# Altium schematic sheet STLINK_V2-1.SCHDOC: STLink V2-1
size A4; Author: Ph.A; SheetNumber: 7; SheetTotal: 8
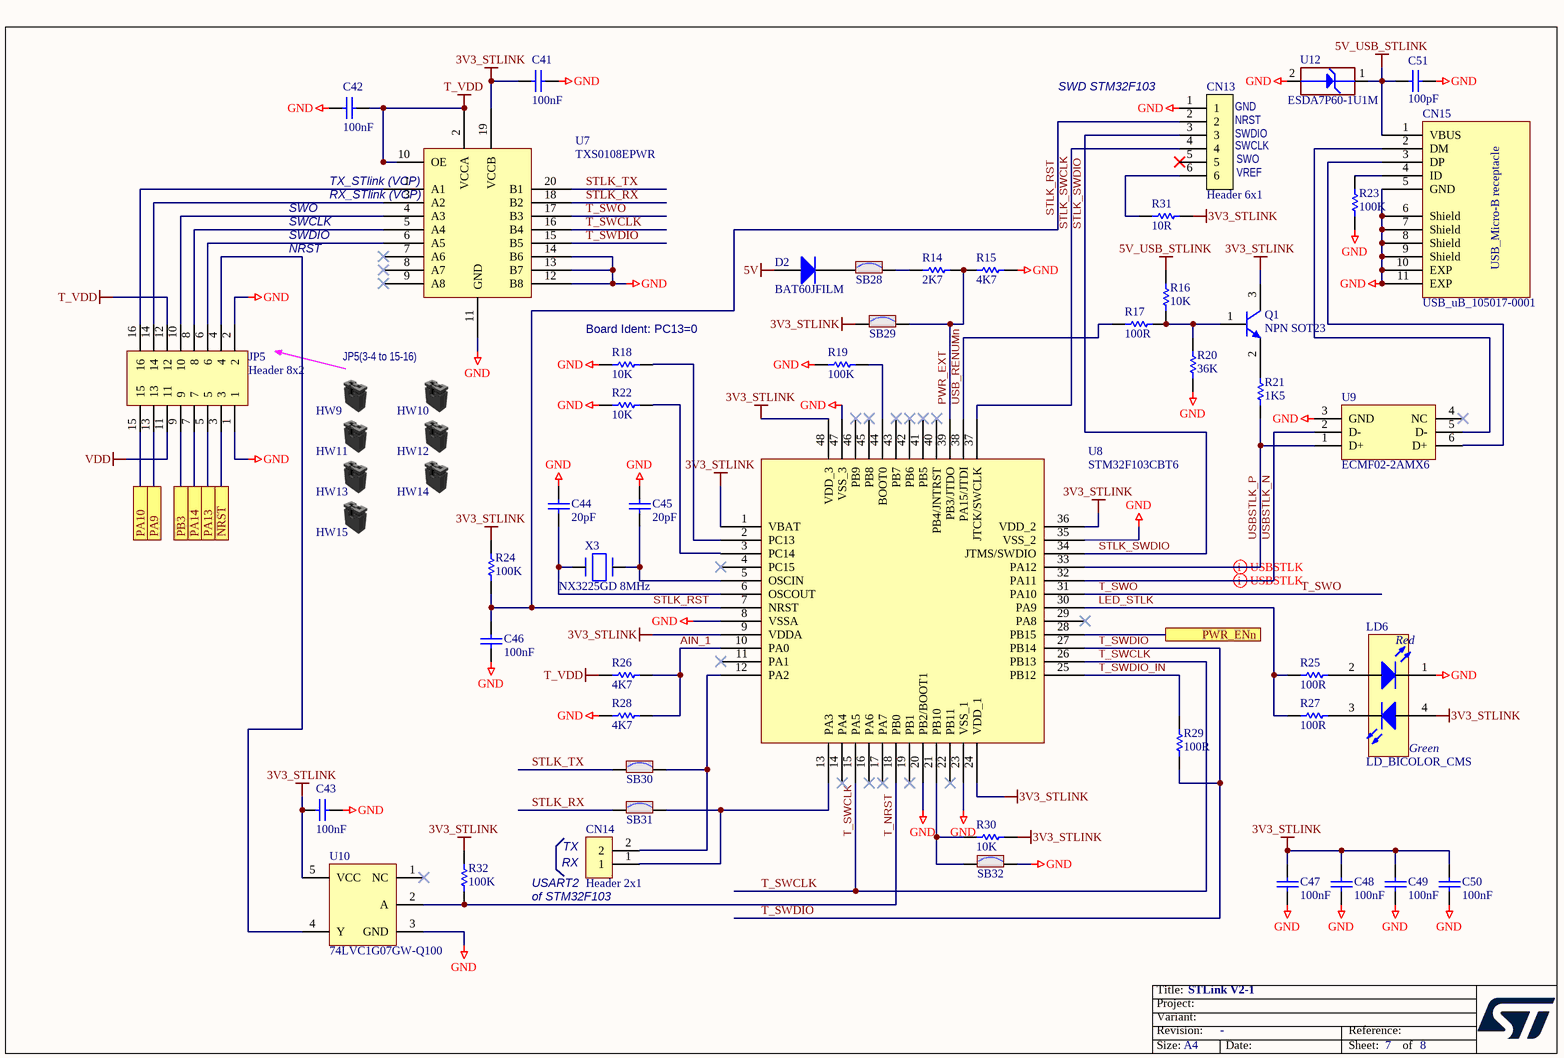
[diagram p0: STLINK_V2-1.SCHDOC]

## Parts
C41  value 100nF  [C0402]  (hidden comment: Capacitor)
C42  value 100nF  [C0402]  (hidden comment: Capacitor)
C43  value 100nF  [C0402]  (hidden comment: Capacitor)
C44  value 20pF  [C0402]  (hidden comment: Capacitor)
C45  value 20pF  [C0402]  (hidden comment: Capacitor)
C46  value 100nF  [C0402]  (hidden comment: Capacitor)
C47  value 100nF  [C0402]  (hidden comment: Capacitor)
C48  value 100nF  [C0402]  (hidden comment: Capacitor)
C49  value 100nF  [C0402]  (hidden comment: Capacitor)
C50  value 100nF  [C0402]  (hidden comment: Capacitor)
C51  value 100pF  [C0402]  (hidden comment: Capacitor)
CN13  Header 6x1  [CON_SAMTEC_TSW-106-07-X-S]
CN14  Header 2x1  [CON_SAMTEC_TSW-102-07-G-S]
CN15  value USB_uB_105017-0001  [CON_USBMICROB_MOLEX_105017-0001_H2P90]  (hidden comment: USB_uB_105017.0001)
D2  BAT60JFILM  [DIO_SOD323]
HW9  Shunt Black 2.54mm  (value not drawn)  (mechanical)
HW10  Shunt Black 2.54mm  (value not drawn)  (mechanical)
HW11  Shunt Black 2.54mm  (value not drawn)  (mechanical)
HW12  Shunt Black 2.54mm  (value not drawn)  (mechanical)
HW13  Shunt Black 2.54mm  (value not drawn)  (mechanical)
HW14  Shunt Black 2.54mm  (value not drawn)  (mechanical)
HW15  Shunt Black 2.54mm  (value not drawn)  (mechanical)
JP5  Header 8x2  [CON_SAMTEC_TSW-108-07-X-D]
LD6  LD_BICOLOR_CMS  [LED_BI-GR_HSMF-A201-A00J1]
Q1  value NPN SOT23  [NPN_SOT23]  (hidden comment: 9013-SOT23)
R14  value 2K7  [R0402]  (hidden comment: Resistor)
R15  value 4K7  [R0402]  (hidden comment: Resistor)
R16  value 10K  [R0402]  (hidden comment: Resistor)
R17  value 100R  [R0402]  (hidden comment: Resistor)
R18  value 10K  [R0402]  (hidden comment: Resistor)
R19  value 100K  [R0402]  (hidden comment: Resistor)
R20  value 36K  [R0402]  (hidden comment: Resistor)
R21  value 1K5  [R0402]  (hidden comment: Resistor)
R22  value 10K  [R0402]  (hidden comment: Resistor)
R23  value 100K  [R0402]  (hidden comment: Resistor)
R24  value 100K  [R0402]  (hidden comment: Resistor)
R25  value 100R  [R0402]  (hidden comment: Resistor)
R26  value 4K7  [R0402]  (hidden comment: Resistor)
R27  value 100R  [R0402]  (hidden comment: Resistor)
R28  value 4K7  [R0402]  (hidden comment: Resistor)
R29  value 100R  [R0402]  (hidden comment: Resistor)
R30  value 10K  [R0402]  (hidden comment: Resistor)
R31  value 10R  [R0402]  (hidden comment: Resistor)
R32  value 100K  [R0402]  (hidden comment: Resistor)
SB28  SB_ON  [SOLDER-BRIDGE_R0402-0R]  (value not drawn)
SB29  SB_ON  [SOLDER-BRIDGE_R0402-0R]  (value not drawn)
SB30  SB_ON  [SOLDER-BRIDGE_R0402-0R]  (value not drawn)
SB31  SB_ON  [SOLDER-BRIDGE_R0402-0R]  (value not drawn)
SB32  SB_ON  [SOLDER-BRIDGE_R0402-0R]  (value not drawn)
U7  TXS0108EPWR  [ICC_TSSOP20_6P50X4P40_P065]
U8  STM32F103CBT6  [ICC_LQFP48_7X7_P050]
U9  ECMF02-2AMX6  [ESD_QFN-6L_1P7X1P5_P050]
U10  74LVC1G07GW-Q100  [ICC_TSSOP5_SOT353-1_2P05X1P25_P065]
U12  value ESDA7P60-1U1M  [ESD_QFN2_1P6X1_P125]  (hidden comment: ESD-TRANSIL)
X3  value NX3225GD 8MHz  [CRY_NX3225GD_2P]  (hidden comment: XTAL_2_PINS)

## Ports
NRST, PA9, PA10, PA13, PA14, PB3, PWR_ENn

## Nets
3V3_STLINK: C41.1 C43.1 C47.2 C48.2 C49.2 C50.2 LD6.4(YellowGreen_anode) Q1.3(C) R24.2 R30.1 R31.2 R32.2 SB29.1 U7.19(VCCB) U8.1(VBAT) U8.9(VDDA) U8.24(VDD_1) U8.36(VDD_2) U8.48(VDD_3) U10.5(VCC)
5V: D2.1(A)
5V_USB_STLINK: C51.1 CN15.1(VBUS) R16.2 U12.1(IO1)
GND: C41.2 C42.1 C43.2 C44.2 C45.2 C46.1 C47.1 C48.1 C49.1 C50.1 C51.2 CN13.1 CN15.5(GND) CN15.6(Shield) CN15.7(Shield) CN15.8(Shield) CN15.9(Shield) CN15.10(EXP) CN15.11(EXP) JP5.1 JP5.2 LD6.1(RED_cathode) R15.2 R18.2 R19.2 R20.1 R22.2 R23.1 R28.1 SB32.2 U7.11(GND) U7.12(B8) U7.13(B7) U7.14(B6) U8.8(VSSA) U8.20(PB2/BOOT1) U8.23(VSS_1) U8.35(VSS_2) U8.47(VSS_3) U9.3(GND) U10.3(GND) U12.2(GND)
T_VDD: C42.2 JP5.12 R26.1 U7.2(VCCA) U7.10(OE)
VDD: JP5.11
AIN_1: R26.2 R28.2 U8.10(PA0)
LED_STLK: R25.1 R27.1 U8.30(PA9)
NRST: JP5.3 ; port NRST
PA9: JP5.13 ; port PA9
PA10: JP5.15 ; port PA10
PA13: JP5.5 ; port PA13
PA14: JP5.7 ; port PA14
PB3: JP5.9 ; port PB3
PWR_ENn: U8.28(PB15) ; port PWR_ENn
PWR_EXT: R14.2 R15.1 SB29.2 U8.39(PB3/JTDO)
STLK_RST: C46.2 CN13.2 R24.1 U8.7(NRST)
STLK_RX: SB31.1 U7.18(B2)
STLK_SWCLK: CN13.4 U8.37(JTCK/SWCLK)
STLK_SWDIO: CN13.3 U8.34(JTMS/SWDIO)
STLK_TX: SB30.1 U7.20(B1)
T_NRST: R32.1 U8.18(PB0) U10.2(A)
T_SWCLK: U7.16(B4) U8.15(PA5) U8.26(PB13)
T_SWDIO: R29.1 U7.15(B5) U8.27(PB14)
T_SWDIO_IN: R29.2 U8.25(PB12)
T_SWO: U7.17(B3) U8.31(PA10)
USB_RENUMn: R17.1 U8.38(PA15/JTDI)
USBSTLK_N: U8.32(PA11) U9.2(D-)
USBSTLK_P: R21.1 U8.33(PA12) U9.1(D+)
NetC44_1: C44.1 U8.6(OSCOUT) X3.1(X1)
NetC45_1: C45.1 U8.5(OSCIN) X3.2(X2)
NetCN13_6: CN13.6 R31.1
NetCN14_1: CN14.1 SB31.2 U8.13(PA3)
NetCN14_2: CN14.2 SB30.2 U8.12(PA2)
NetCN15_2: CN15.2(DM) U9.5(D-)
NetCN15_3: CN15.3(DP) U9.6(D+)
NetCN15_4: CN15.4(ID) R23.2
NetD2_2: D2.2(K) SB28.1
NetJP5_4: JP5.4 U10.4(Y)
NetJP5_6: JP5.6 U7.6(A5)
NetJP5_8: JP5.8 U7.5(A4)
NetJP5_10: JP5.10 U7.4(A3)
NetJP5_14: JP5.14 U7.3(A2)
NetJP5_16: JP5.16 U7.1(A1)
NetLD6_2: LD6.2(Red_anode) R25.2
NetLD6_3: LD6.3(YellowGreen_cathode) R27.2
NetQ1_1: Q1.1(B) R16.1 R17.2 R20.2
NetQ1_2: Q1.2(E) R21.2
NetR14_1: R14.1 SB28.2
NetR18_1: R18.1 U8.2(PC13)
NetR19_1: R19.1 U8.44(BOOT0)
NetR22_1: R22.1 U8.3(PC14)
NetR30_2: R30.2 SB32.1 U8.21(PB10)

Not connected (* = marked no-connect by the designer): CN13 5*; U7 7(A6)* 8(A7)* 9(A8)*; U8 4(PC15)* 11(PA1)* 14(PA4)* 16(PA6)* 17(PA7)* 19(PB1)* 22(PB11)* 29(PA8)* 40(PB4/JNTRST)* 41(PB5)* 42(PB6)* 43(PB7)* 45(PB8)* 46(PB9)*; U9 4(NC)*; U10 1(NC)*

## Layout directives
differential pair; net class DIFF90: USBSTLK_N, USBSTLK_P

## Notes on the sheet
- SWD STM32F103
- (near CN13) SWDIO
- (near CN13) NRST
- (near CN13) GND
- TX_STlink (VCP)
- RX_STlink (VCP)
- (near CN13) SWCLK
- (near CN13) SWO
- (near CN13) VREF
- SWO
- SWCLK
- SWDIO
- NRST
- (near R18) Board Ident: PC13=0
- JP5(3-4 to 15-16)
- (near CN14) RX
- TX
- USART2
- (near CN14) of STM32F103

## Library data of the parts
C41-C43 C46-C50 = MCD-00006: Capacitor, MLCC, 100nF, 16V, X7R, +/-10%, 0402, T=0.5mm; Manufacturer_Part_Number: CC0402KRX7R7BB104; Manufacturer: YAGEO; Alternate_Manufacturer_Part_Number: GCM155R71C104KA55D; Alternate_Manufacturer: MURATA; Part_Preference: Recommended; Order_Code_RS: 616-9701
C44 C45 = MCD-00016: Capacitor, MLCC, 20pF, 50V, NPO, +/- 5%, 0402, T=0,5mm; Manufacturer_Part_Number: CC0402JRNPO9BN200; Manufacturer: YAGEO; Part_Preference: Recommended
C51 = MCD-00205: Capacitor,MLCC,100pF,50V,NPO,+/-5%,0402,T=0,5mm; Manufacturer_Part_Number: CC0402JRNPO9BN101; Manufacturer: YAGEO; Part_Preference: Recommended
CN13 = MCD-00212: Header, 6x1, 2,54mm, VR, TH, Height 5.84mm/2.54mm; Part_Type: Connector; Manufacturer_Part_Number: TSW-106-07-G-S; Manufacturer: SAMTEC; Part_Preference: Recommended
CN14 = MCD-00032: Header, 2x1, 2,54mm, VR, TH, Height 5.84mm/2.54mm; Manufacturer_Part_Number: TSW-102-07-G-S; Manufacturer: SAMTEC; Part_Type: Connector; Part_Preference: Recommended; Alternate_Manufacturer: JIUBABA; Alternate_Manufacturer_Part_Number: 313102S111116
CN15 = MCD-00028: USB-MICRO-B, 0.65mm, RA, SMT, Bottom Mount,; Part_Type: Connector; Manufacturer_Part_Number: 1050170001; Manufacturer: MOLEX; Part_Preference: Recommended
D2 = MCD-00034: Manufacturer: STMICROELECTRONICS; Part_Type: Diode; BMS_Part_Number: 9151097; Part_Preference: Recommended; Manufacturer_HQ_COO: EU
HW9-HW15 = MCD-00043: SHUNT 2.54mm BLACK; Manufacturer_Part_Number: SNT-100-BK-G; Manufacturer: SAMTEC; Part_Type: Misc; Part_Preference: Recommended; Alternate_Manufacturer: JIUBABA; Alternate_Manufacturer_Part_Number: 316102S111A; Value: SNT-100-BK-G
JP5 = MCD-02061: Header, 8x2, 2,54mm, VR, TH, Height 5.84mm/2.54mm; Part_Type: Connector; Manufacturer_Part_Number: TSW-108-07-G-D; Manufacturer: SAMTEC; Part_Preference: Recommended; Order_Code_RS: 161-2292
LD6 = MCD-00051: LED Bicolor; Part_Type: Display; Manufacturer_Part_Number: HSMF-A201-A00J1; Manufacturer: AVAGO TECHNOLOGIES; Alternate_Manufacturer_Part_Number: LE-RGW35280; Alternate_Manufacturer: EVERLUCK; Part_Preference: Forbidden
Q1 = MCD-00073: NPN Bipolar Transistor; Manufacturer_Part_Number: BSR14; Manufacturer: ON SEMICONDUCTOR; Part_Type: IC; Part_Preference: Recommended; Alternate_Manufacturer_Part_Number: MMBT2222LT1G / MMBT2222ALT1G / MMBT2222ALT3G
R14 = MCD-00055: Resistor,2K7,0402,1%,1/16W; Manufacturer_Part_Number: RC0402FR-072K7L; Manufacturer: YAGEO; Part_Preference: Recommended
R15 R26 R28 = MCD-00065: Resistor,4K7,0402,1%,1/16W; Manufacturer_Part_Number: RC0402FR-074K7L; Manufacturer: YAGEO; Alternate_Manufacturer_Part_Number: RT0402FRE074K7L; Part_Preference: Recommended
R16 R18 R22 R30 = MCD-00053: Resistor,10K,0402,1%,1/16W; Manufacturer_Part_Number: RC0402FR-0710KL; Manufacturer: YAGEO; BMS_Part_Number: 9131590; Part_Preference: Recommended
R17 R25 R27 R29 = MCD-00067: Resistor,100R,0402,1%,1/16W; Manufacturer_Part_Number: RC0402FR-07100RL; Manufacturer: YAGEO; Part_Preference: Recommended
R19 R23 R24 R32 = MCD-00059: Resistor,100K,0402,1%,1/16W; Manufacturer_Part_Number: RC0402FR-07100KL; Manufacturer: YAGEO; Alternate_Manufacturer_Part_Number: RT0402FRE07100KL; Part_Preference: Recommended
R20 = MCD-00069: Resistor,36K,0402,1%,1/16W; Manufacturer_Part_Number: RC0402FR-0736KL; Manufacturer: YAGEO; Part_Preference: Recommended
R21 = MCD-00068: Resistor,1K5,0402,1%,1/16W; Manufacturer_Part_Number: RC0402FR-071K5L; Manufacturer: YAGEO; Part_Preference: Recommended
R31 = MCD-00358: Resistor,10R,0402,1%,1/16W; Manufacturer_Part_Number: RC0402FR-0710RL; Manufacturer: YAGEO; Part_Preference: Recommended; Order_Code_RS: 618-5848
SB28-SB32 = MCD-01618: Solder Bridge 0402 ON; Part_Type: Misc; Manufacturer_Part_Number: RC0402JR-070RL; Manufacturer: YAGEO; Part_Preference: Recommended; Order_Code_RS: 618-5804
U7 = MCD-00289: 8bits_bidirectionnal level shifter, Delay 312ns/1V8; Part_Type: IC; Manufacturer: TEXAS INSTRUMENTS; Part_Preference: Recommended
U8 = MCD-00085: Medium-density performance line ARM-based 32-bit MCU with 128KB Flash; Part_Type: IC; Manufacturer: STMICROELECTRONICS; BMS_Part_Number: 9175111; Part_Preference: Recommended; Manufacturer_HQ_COO: EU
U9 = MCD-00649: Common mode filter with ESD protection for USB 2.0 interface; Part_Type: Diode; Manufacturer: STMICROELECTRONICS; BMS_Part_Number: 9151138; Part_Preference: Recommended; Manufacturer_HQ_COO: EU
U10 = MCD-01960: Buffer/Driver 1-CH Non-Inverting Open Drain CMOS Automotive 5-Pin TSSOP T/R; Part_Type: IC; Manufacturer: NEXPERIA; Part_Preference: Recommended
U12 = MCD-00251: High power transient voltage suppressor, 7V breakdown; Part_Type: Diode; Manufacturer: STMICROELECTRONICS; BMS_Part_Number: 9179042; Part_Preference: Recommended; Manufacturer_HQ_COO: EU
X3 = MCD-00092: Crystal 8MHz, 8pF, +-20ppm, 500ohms max,  SMD; Part_Type: Crystal oscillator; Manufacturer_Part_Number: NX3225GD 8MHz EXS00A-CG04874; Manufacturer: NDK; BMS_Part_Number: 9157029; Part_Preference: Recommended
